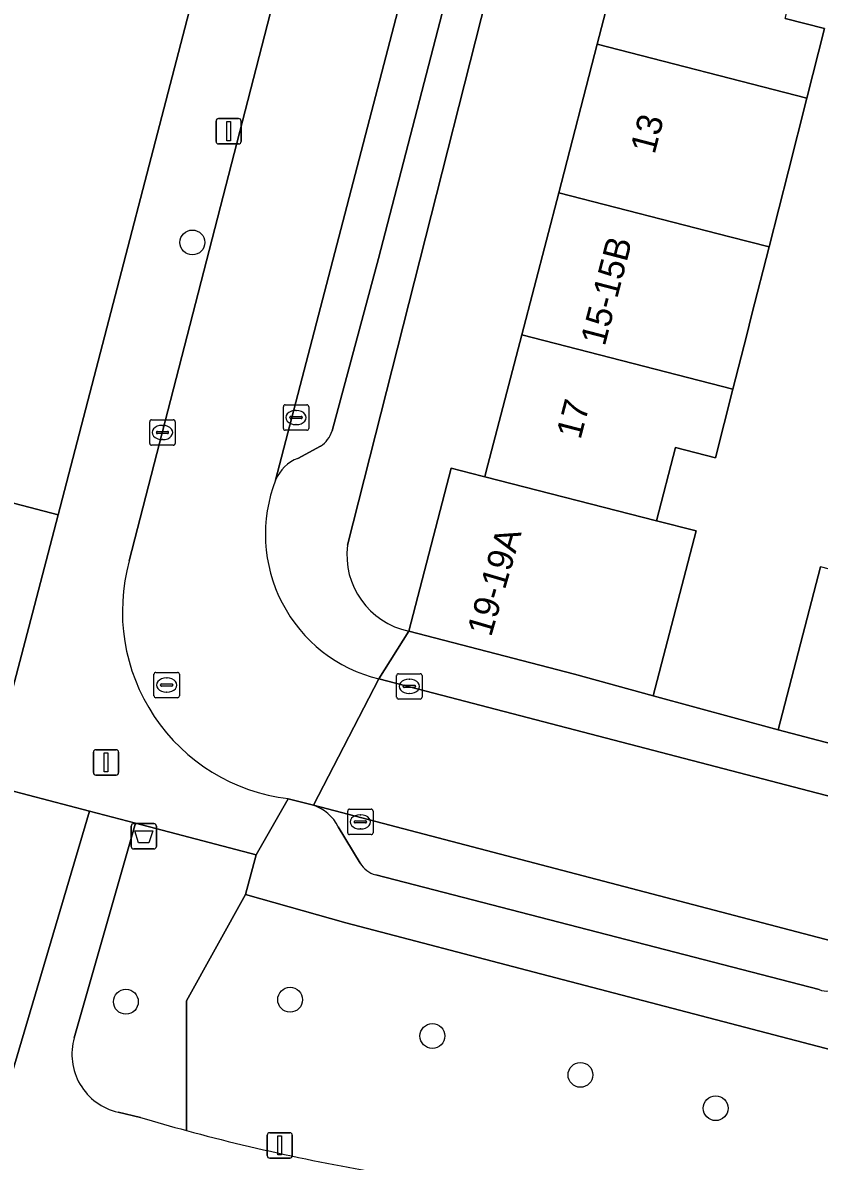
# Model space of a CAD drawing. Extents: x 163683 to 164494, y 382709 to 383872.
# Drawn here: x 164168.99 to 164200.33, y 383077.5 to 383122.29 of the extents above; entities that cross this region are included whole.
import ezdxf

# ---------------------------------------------------------------- set-up
doc = ezdxf.new("R2010")
doc.units = 0
for name, color, linetype in [('IMGEO_Afvalbak', 7, 'Continuous'), ('IMGEO_Boom', 7, 'Continuous'), ('IMGEO_Erf', 7, 'Continuous'), ('IMGEO_Groenvoorziening', 7, 'Continuous'), ('IMGEO_Kolk', 7, 'Continuous'), ('IMGEO_Lichtmast', 7, 'Continuous'), ('IMGEO_Muur', 7, 'Continuous'), ('IMGEO_Pand', 7, 'Continuous'), ('IMGEO_Pand_nummerreeks', 7, 'Continuous'), ('IMGEO_Parkeervlak_open', 7, 'Continuous'), ('IMGEO_Rijbaan_lokaal_open', 7, 'Continuous'), ('IMGEO_Rioolput', 7, 'Continuous'), ('IMGEO_Voetpad_halfverhard', 7, 'Continuous'), ('IMGEO_Voetpad_open', 7, 'Continuous')]:
    doc.layers.add(name, color=color, linetype=linetype)

msp = doc.modelspace()

# ---------------------------------------------------------------- linework, layer by layer
at = {"layer": 'IMGEO_Afvalbak'}
for p, q in [((164173.259, 383089.882), (164173.259, 383090.682)), ((164173.259, 383090.682), (164173.259, 383089.882)), ((164173.359, 383090.782), (164174.149, 383090.782)), ((164174.149, 383090.782), (164173.359, 383090.782)), ((164174.249, 383090.682), (164174.249, 383089.882)), ((164174.249, 383089.882), (164174.249, 383090.682)), ((164174.149, 383089.782), (164173.359, 383089.782)), ((164173.359, 383089.782), (164174.149, 383089.782))]:
    msp.add_line(p, q, dxfattribs=at)
msp.add_lwpolyline([(164173.402, 383090.496), (164174.106, 383090.496), (164173.957, 383090.026), (164173.551, 383090.026), (164173.402, 383090.496)], dxfattribs=at)
for centre, start, end in [((164173.359, 383090.682), 90, 180), ((164173.359, 383090.682), 90, 180), ((164174.149, 383090.682), 0, 90), ((164174.149, 383090.682), 360, 90), ((164173.359, 383089.882), 180, 270), ((164173.359, 383089.882), 180, 270), ((164174.149, 383089.882), 270, 0), ((164174.149, 383089.882), 270, 0)]:
    msp.add_arc(centre, 0.1, start, end, dxfattribs=at)
at = {"layer": 'IMGEO_Boom'}
for centre in [(164175.667, 383113.644), (164173.05, 383083.771), (164179.513, 383083.851), (164185.111, 383082.424), (164190.938, 383080.895), (164196.258, 383079.583)]:
    msp.add_circle(centre, 0.489, dxfattribs=at)
at = {"layer": 'IMGEO_Erf'}
for points in [[(164235.416, 383087.174), (164249.772, 383143.475), (164225.172, 383149.691), (164224.38, 383146.62), (164220.869, 383147.526), (164218.278, 383138.676), (164221.781, 383137.775), (164221.055, 383134.95), (164220.387, 383132.353), (164217.268, 383133.155), (164217.081, 383132.425), (164215.494, 383132.833), (164216.241, 383135.98), (164212.881, 383136.834), (164213.61, 383139.702), (164214.266, 383142.284), (164217.626, 383141.431), (164219.349, 383147.981), (164215.956, 383148.856), (164216.694, 383151.712), (164199.271, 383156.404), (164196.004, 383157.255), (164190.094, 383134.558), (164181.769, 383101.734)], [(164184.184, 383098.352), (164185.85, 383104.765), (164187.07, 383104.45), (164187.177, 383104.422), (164187.22, 383104.589), (164188.627, 383110.009), (164190.08, 383115.601), (164191.597, 383121.443), (164193.013, 383126.897)], [(164198.994, 383122.461), (164200.544, 383122.066), (164199.846, 383119.322), (164199.119, 383116.464), (164198.358, 383113.473), (164197.67, 383110.766), (164197.479, 383110.016), (164196.934, 383107.873), (164196.247, 383105.17), (164194.679, 383105.577), (164193.928, 383102.686), (164195.489, 383102.294), (164193.804, 383095.809), (164198.713, 383094.463), (164200.381, 383100.884)]]:
    msp.add_lwpolyline(points, dxfattribs=at)
msp.add_arc((164184.81, 383101.352), 3.065, 172.8489, 258.2105, dxfattribs=at)
at = {"layer": 'IMGEO_Groenvoorziening'}
for points in [[(164176.537, 383126.569), (164154.315, 383132.306), (164153.975, 383138.872), (164152.776, 383139.237), (164150.9, 383131.848), (164147.04, 383116.646), (164145.764, 383116.973), (164145.551, 383116.143), (164148.108, 383115.477), (164150.025, 383115.042), (164150.47, 383114.883), (164148.895, 383108.547), (164170.385, 383102.927)], [(164130.601, 383105.021), (164153.924, 383098.841), (164168.382, 383095.258), (164169.377, 383099.053), (164170.385, 383102.927), (164148.895, 383108.547), (164150.47, 383114.883), (164150.025, 383115.042), (164148.108, 383115.477), (164145.551, 383116.143), (164143.667, 383108.811), (164132.278, 383111.736)]]:
    msp.add_lwpolyline(points, close=True, dxfattribs=at)
for points in [[(164168.497, 383080.71), (164171.615, 383091.268), (164167.61, 383092.316), (164165.451, 383091.845)], [(164177.759, 383087.988), (164178.183, 383089.55), (164173.426, 383090.794), (164171.016, 383082.356)], [(164184.316, 383076.837), (164200.329, 383074.759), (164202.426, 383081.458), (164200.547, 383081.949), (164189.122, 383084.931), (164181.701, 383086.88), (164177.759, 383087.988), (164175.432, 383083.801), (164175.432, 383078.705)], [(164175.432, 383078.705), (164175.432, 383083.801), (164177.759, 383087.988)], [(164172.74, 383079.423), (164173.631, 383079.214)]]:
    msp.add_lwpolyline(points, dxfattribs=at)
for centre, radius, start, end in [((164173.276, 383081.711), 2.35, 164.0721, 256.8215), ((164195.419, 383152.866), 76.807, 253.52053, 254.91668), ((164196.337, 383156.069), 80.139, 254.87862, 261.37267)]:
    msp.add_arc(centre, radius, start, end, dxfattribs=at)
at = {"layer": 'IMGEO_Kolk'}
for p, q in [((164179.246, 383106.331), (164179.246, 383107.183)), ((164179.321, 383107.257), (164180.173, 383107.257)), ((164180.247, 383107.183), (164180.247, 383106.331)), ((164174.064, 383106.667), (164174.916, 383106.667)), ((164179.505, 383106.751), (164179.505, 383106.763)), ((164179.943, 383106.714), (164179.545, 383106.714)), ((164179.548, 383106.8), (164179.946, 383106.8)), ((164179.734, 383107.037), (164179.759, 383107.037)), ((164179.989, 383106.763), (164179.989, 383106.751)), ((164173.989, 383105.741), (164173.989, 383106.593)), ((164174.291, 383106.21), (164174.689, 383106.21)), ((164174.477, 383106.447), (164174.502, 383106.447)), ((164174.99, 383106.593), (164174.99, 383105.741)), ((164180.173, 383106.257), (164179.321, 383106.257)), ((164179.757, 383106.477), (164179.732, 383106.477)), ((164174.248, 383106.161), (164174.248, 383106.173)), ((164174.686, 383106.124), (164174.288, 383106.124)), ((164174.5, 383105.887), (164174.475, 383105.887)), ((164174.732, 383106.173), (164174.732, 383106.161)), ((164174.916, 383105.667), (164174.064, 383105.667)), ((164183.705, 383095.752), (164183.705, 383096.604)), ((164183.78, 383096.678), (164184.632, 383096.678)), ((164184.193, 383096.458), (164184.218, 383096.458)), ((164184.706, 383096.604), (164184.706, 383095.752)), ((164183.964, 383096.172), (164183.964, 383096.184)), ((164184.402, 383096.135), (164184.004, 383096.135)), ((164184.007, 383096.221), (164184.405, 383096.221)), ((164184.216, 383095.898), (164184.191, 383095.898)), ((164184.448, 383096.184), (164184.448, 383096.172)), ((164184.632, 383095.678), (164183.78, 383095.678)), ((164181.778, 383090.422), (164181.778, 383091.274)), ((164181.853, 383091.348), (164182.705, 383091.348)), ((164182.266, 383091.128), (164182.291, 383091.128)), ((164182.779, 383091.274), (164182.779, 383090.422)), ((164182.037, 383090.842), (164182.037, 383090.854)), ((164182.475, 383090.805), (164182.077, 383090.805)), ((164182.08, 383090.891), (164182.478, 383090.891)), ((164182.289, 383090.568), (164182.264, 383090.568)), ((164182.521, 383090.854), (164182.521, 383090.842)), ((164182.705, 383090.348), (164181.853, 383090.348))]:
    msp.add_line(p, q, dxfattribs=at)
for points in [[(164179.246, 383106.331), (164179.246, 383107.183)], [(164179.321, 383107.257), (164180.173, 383107.257)], [(164180.247, 383107.183), (164180.247, 383106.331)], [(164174.064, 383106.667), (164174.916, 383106.667)], [(164173.989, 383105.741), (164173.989, 383106.593)], [(164174.99, 383106.593), (164174.99, 383105.741)], [(164180.173, 383106.257), (164179.321, 383106.257)], [(164174.916, 383105.667), (164174.064, 383105.667)], [(164183.705, 383095.752), (164183.705, 383096.604)], [(164183.78, 383096.678), (164184.632, 383096.678)], [(164184.706, 383096.604), (164184.706, 383095.752)], [(164184.632, 383095.678), (164183.78, 383095.678)], [(164181.778, 383090.422), (164181.778, 383091.274)], [(164181.853, 383091.348), (164182.705, 383091.348)], [(164182.779, 383091.274), (164182.779, 383090.422)], [(164182.705, 383090.348), (164181.853, 383090.348)]]:
    msp.add_lwpolyline(points, dxfattribs=at)
for centre, radius, start, end in [((164179.323, 383107.181), 0.0765, 91.552, 178.448), ((164179.323, 383107.181), 0.0765, 91.552, 178.448), ((164180.171, 383107.181), 0.0765, 1.552, 88.448), ((164180.171, 383107.181), 0.0765, 1.552, 88.448), ((164174.066, 383106.591), 0.0765, 91.552, 178.448), ((164174.066, 383106.591), 0.0765, 91.552, 178.448), ((164174.914, 383106.591), 0.0765, 1.552, 88.448), ((164174.914, 383106.591), 0.0765, 1.552, 88.448), ((164179.545, 383106.76), 0.0403, 85.8775, 175.7526), ((164179.542, 383106.75), 0.0366, 178.938, 274.7102), ((164179.946, 383106.757), 0.043, 264.8664, 352.4533), ((164179.95, 383106.762), 0.0386, 1.7309, 96.639), ((164174.288, 383106.17), 0.0403, 85.8775, 175.7526), ((164174.693, 383106.172), 0.0386, 1.7309, 96.639), ((164179.323, 383106.333), 0.0765, 181.552, 268.448), ((164179.323, 383106.333), 0.0765, 181.552, 268.448), ((164180.171, 383106.333), 0.0765, 271.552, 358.448), ((164180.171, 383106.333), 0.0765, 271.552, 358.448), ((164174.066, 383105.743), 0.0765, 181.552, 268.448), ((164174.066, 383105.743), 0.0765, 181.552, 268.448), ((164174.285, 383106.16), 0.0366, 178.938, 274.7102), ((164174.689, 383106.167), 0.043, 264.8664, 352.4533), ((164174.914, 383105.743), 0.0765, 271.552, 358.448), ((164174.914, 383105.743), 0.0765, 271.552, 358.448), ((164183.782, 383096.602), 0.0765, 91.552, 178.448), ((164183.782, 383096.602), 0.0765, 91.552, 178.448), ((164184.63, 383096.602), 0.0765, 1.552, 88.448), ((164184.63, 383096.602), 0.0765, 1.552, 88.448), ((164184.004, 383096.181), 0.0403, 85.8775, 175.7526), ((164184.001, 383096.171), 0.0366, 178.938, 274.7102), ((164184.405, 383096.178), 0.043, 264.8664, 352.4533), ((164184.409, 383096.183), 0.0386, 1.7309, 96.639), ((164183.782, 383095.754), 0.0765, 181.552, 268.448), ((164183.782, 383095.754), 0.0765, 181.552, 268.448), ((164184.63, 383095.754), 0.0765, 271.552, 358.448), ((164184.63, 383095.754), 0.0765, 271.552, 358.448), ((164181.855, 383091.272), 0.0765, 91.552, 178.448), ((164181.855, 383091.272), 0.0765, 91.552, 178.448), ((164182.703, 383091.272), 0.0765, 1.552, 88.448), ((164182.703, 383091.272), 0.0765, 1.552, 88.448), ((164182.077, 383090.851), 0.0403, 85.8775, 175.7526), ((164182.074, 383090.841), 0.0366, 178.938, 274.7102), ((164182.478, 383090.848), 0.043, 264.8664, 352.4533), ((164182.482, 383090.853), 0.0386, 1.7309, 96.639), ((164181.855, 383090.424), 0.0765, 181.552, 268.448), ((164181.855, 383090.424), 0.0765, 181.552, 268.448), ((164182.703, 383090.424), 0.0765, 271.552, 358.448), ((164182.703, 383090.424), 0.0765, 271.552, 358.448)]:
    msp.add_arc(centre, radius, start, end, dxfattribs=at)
for centre, major_axis, ratio, start_param, end_param in [((164179.733, 383106.757), (-0.387, 0.002), 0.722429, 4.712389, 7.853982), ((164179.758, 383106.757), (-0.39, 0.002), 0.717154, 1.570796, 4.712389), ((164174.476, 383106.167), (-0.387, 0.002), 0.722429, 4.712389, 7.853982), ((164174.501, 383106.167), (-0.39, 0.002), 0.717154, 1.570796, 4.712389), ((164184.192, 383096.178), (-0.387, 0.002), 0.722429, 4.712389, 7.853982), ((164184.217, 383096.178), (-0.39, 0.002), 0.717154, 1.570796, 4.712389), ((164182.265, 383090.848), (-0.387, 0.002), 0.722429, 4.712389, 7.853982), ((164182.29, 383090.848), (-0.39, 0.002), 0.717154, 1.570796, 4.712389)]:
    msp.add_ellipse(centre, major_axis=major_axis, ratio=ratio, start_param=start_param, end_param=end_param, dxfattribs=at)
at = {"layer": 'IMGEO_Lichtmast'}
for p, q in [((164176.597, 383117.622), (164176.597, 383118.422)), ((164176.597, 383118.422), (164176.597, 383117.622)), ((164176.697, 383118.522), (164177.487, 383118.522)), ((164177.487, 383118.522), (164176.697, 383118.522)), ((164177.587, 383118.422), (164177.587, 383117.622)), ((164177.587, 383117.622), (164177.587, 383118.422)), ((164177.487, 383117.522), (164176.697, 383117.522)), ((164176.697, 383117.522), (164177.487, 383117.522)), ((164171.873, 383093.687), (164172.663, 383093.687)), ((164172.663, 383093.687), (164171.873, 383093.687)), ((164171.773, 383092.787), (164171.773, 383093.587)), ((164171.773, 383093.587), (164171.773, 383092.787)), ((164172.763, 383093.587), (164172.763, 383092.787)), ((164172.763, 383092.787), (164172.763, 383093.587)), ((164172.663, 383092.687), (164171.873, 383092.687)), ((164171.873, 383092.687), (164172.663, 383092.687)), ((164178.609, 383077.717), (164178.609, 383078.517)), ((164178.609, 383078.517), (164178.609, 383077.717)), ((164178.709, 383078.617), (164179.499, 383078.617)), ((164179.499, 383078.617), (164178.709, 383078.617)), ((164179.599, 383078.517), (164179.599, 383077.717)), ((164179.599, 383077.717), (164179.599, 383078.517)), ((164179.499, 383077.617), (164178.709, 383077.617)), ((164178.709, 383077.617), (164179.499, 383077.617))]:
    msp.add_line(p, q, dxfattribs=at)
for points in [[(164177.017, 383118.397), (164177.167, 383118.397), (164177.167, 383117.647), (164177.017, 383117.647), (164177.017, 383118.397)], [(164172.193, 383093.562), (164172.343, 383093.562), (164172.343, 383092.812), (164172.193, 383092.812), (164172.193, 383093.562)], [(164179.029, 383078.492), (164179.179, 383078.492), (164179.179, 383077.742), (164179.029, 383077.742), (164179.029, 383078.492)]]:
    msp.add_lwpolyline(points, dxfattribs=at)
for centre, start, end in [((164176.697, 383118.422), 90, 180), ((164176.697, 383118.422), 90, 180), ((164177.487, 383118.422), 0, 90), ((164177.487, 383118.422), 360, 90), ((164176.697, 383117.622), 180, 270), ((164176.697, 383117.622), 180, 270), ((164177.487, 383117.622), 270, 0), ((164177.487, 383117.622), 270, 0), ((164171.873, 383093.587), 90, 180), ((164171.873, 383093.587), 90, 180), ((164172.663, 383093.587), 0, 90), ((164172.663, 383093.587), 360, 90), ((164171.873, 383092.787), 180, 270), ((164171.873, 383092.787), 180, 270), ((164172.663, 383092.787), 270, 0), ((164172.663, 383092.787), 270, 0), ((164178.709, 383078.517), 90, 180), ((164178.709, 383078.517), 90, 180), ((164179.499, 383078.517), 0, 90), ((164179.499, 383078.517), 360, 90), ((164178.709, 383077.717), 180, 270), ((164178.709, 383077.717), 180, 270), ((164179.499, 383077.717), 270, 0), ((164179.499, 383077.717), 270, 0)]:
    msp.add_arc(centre, 0.1, start, end, dxfattribs=at)
at = {"layer": 'IMGEO_Muur'}
msp.add_lwpolyline([(164193.804, 383095.809), (164198.713, 383094.463)], dxfattribs=at)
at = {"layer": 'IMGEO_Pand'}
for points in [[(164199.846, 383119.322), (164200.544, 383122.066), (164198.994, 383122.461), (164199.676, 383125.184), (164193.013, 383126.897), (164191.597, 383121.443)], [(164199.846, 383119.322), (164191.597, 383121.443), (164190.08, 383115.601), (164196.809, 383113.871), (164198.358, 383113.473), (164199.119, 383116.464)], [(164198.358, 383113.473), (164196.809, 383113.871), (164190.08, 383115.601), (164188.627, 383110.009), (164196.934, 383107.873), (164197.479, 383110.016), (164197.67, 383110.766)], [(164194.679, 383105.577), (164196.247, 383105.17), (164196.934, 383107.873), (164188.627, 383110.009), (164187.22, 383104.589), (164187.177, 383104.422), (164193.928, 383102.686)], [(164195.489, 383102.294), (164193.928, 383102.686), (164187.177, 383104.422), (164187.07, 383104.45), (164185.85, 383104.765), (164184.184, 383098.352), (164190.698, 383096.66), (164193.804, 383095.809)], [(164201.862, 383093.645), (164203.53, 383100.066), (164200.381, 383100.884), (164198.713, 383094.463)]]:
    msp.add_lwpolyline(points, close=True, dxfattribs=at)
at = {"layer": 'IMGEO_Parkeervlak_open'}
for points in [[(164181.165, 383106.231), (164182.993, 383113.017), (164188.276, 383133.387), (164186.93, 383133.713), (164187.272, 383134.967), (164188.588, 383134.63), (164190.203, 383140.877), (164188.616, 383141.38), (164184.638, 383126.187), (164178.941, 383104.293)], [(164179.817, 383105.151), (164180.712, 383105.627)], [(164227.179, 383079.262), (164180.429, 383091.502)], [(164181.407, 383090.659), (164182.27, 383089.23)], [(164182.88, 383088.767), (164200.333, 383084.249)]]:
    msp.add_lwpolyline(points, dxfattribs=at)
for centre, radius, start, end in [((164180.073, 383106.578), 1.145, 303.8856, 342.3746), ((164180.38, 383103.7), 1.556, 111.2012, 157.6093), ((164179.865, 383089.859), 1.737, 27.4154, 71.0643), ((164183.088, 383089.674), 0.931, 208.5109, 257.0909), ((164200.618, 383084.951), 0.758, 247.9282, 307.1195)]:
    msp.add_arc(centre, radius, start, end, dxfattribs=at)
at = {"layer": 'IMGEO_Rijbaan_lokaal_open'}
for points in [[(164184.638, 383126.187), (164179.925, 383127.281), (164173.185, 383101.113)], [(164178.941, 383104.293), (164184.638, 383126.187)], [(164179.441, 383091.761), (164180.429, 383091.502), (164183.001, 383096.472)], [(164232.76, 383083.491), (164210.131, 383089.408), (164205.194, 383090.692), (164183.001, 383096.472), (164180.429, 383091.502), (164227.179, 383079.262), (164228.673, 383078.974), (164230.667, 383078.411), (164236.737, 383076.868)]]:
    msp.add_lwpolyline(points, dxfattribs=at)
for centre, radius, start, end in [((164184.397, 383102.161), 5.858, 158.6549, 256.2142), ((164180.328, 383099.123), 7.415, 164.4345, 263.1264)]:
    msp.add_arc(centre, radius, start, end, dxfattribs=at)
at = {"layer": 'IMGEO_Rioolput'}
for p, q in [((164174.156, 383095.804), (164174.156, 383096.656)), ((164174.231, 383096.73), (164175.083, 383096.73)), ((164174.644, 383096.51), (164174.669, 383096.51)), ((164175.157, 383096.656), (164175.157, 383095.804)), ((164174.415, 383096.224), (164174.415, 383096.236)), ((164174.853, 383096.187), (164174.455, 383096.187)), ((164174.458, 383096.273), (164174.856, 383096.273)), ((164174.667, 383095.95), (164174.642, 383095.95)), ((164174.899, 383096.236), (164174.899, 383096.224)), ((164175.083, 383095.73), (164174.231, 383095.73))]:
    msp.add_line(p, q, dxfattribs=at)
for points in [[(164174.156, 383095.804), (164174.156, 383096.656)], [(164174.231, 383096.73), (164175.083, 383096.73)], [(164175.157, 383096.656), (164175.157, 383095.804)], [(164175.083, 383095.73), (164174.231, 383095.73)]]:
    msp.add_lwpolyline(points, dxfattribs=at)
for centre, radius, start, end in [((164174.233, 383096.654), 0.0765, 91.552, 178.448), ((164174.233, 383096.654), 0.0765, 91.552, 178.448), ((164175.081, 383096.654), 0.0765, 1.552, 88.448), ((164175.081, 383096.654), 0.0765, 1.552, 88.448), ((164174.455, 383096.233), 0.0403, 85.8775, 175.7526), ((164174.452, 383096.223), 0.0366, 178.938, 274.7102), ((164174.856, 383096.23), 0.043, 264.8664, 352.4533), ((164174.86, 383096.235), 0.0386, 1.7309, 96.639), ((164174.233, 383095.806), 0.0765, 181.552, 268.448), ((164174.233, 383095.806), 0.0765, 181.552, 268.448), ((164175.081, 383095.806), 0.0765, 271.552, 358.448), ((164175.081, 383095.806), 0.0765, 271.552, 358.448)]:
    msp.add_arc(centre, radius, start, end, dxfattribs=at)
for centre, major_axis, ratio, start_param, end_param in [((164174.643, 383096.23), (-0.387, 0.002), 0.722429, 4.712389, 7.853982), ((164174.668, 383096.23), (-0.39, 0.002), 0.717154, 1.570796, 4.712389)]:
    msp.add_ellipse(centre, major_axis=major_axis, ratio=ratio, start_param=start_param, end_param=end_param, dxfattribs=at)
at = {"layer": 'IMGEO_Voetpad_halfverhard'}
for points in [[(164171.016, 383082.356), (164173.426, 383090.794), (164171.615, 383091.268), (164168.497, 383080.71)], [(164173.631, 383079.214), (164172.74, 383079.423)]]:
    msp.add_lwpolyline(points, dxfattribs=at)
for centre, radius, start, end in [((164173.276, 383081.711), 2.35, 164.0721, 256.8215), ((164195.419, 383152.866), 76.807, 253.52053, 254.91668), ((164196.337, 383156.069), 80.139, 254.87862, 261.37267)]:
    msp.add_arc(centre, radius, start, end, dxfattribs=at)
at = {"layer": 'IMGEO_Voetpad_open'}
for points in [[(164194.463, 383158.425), (164194.849, 383158.324), (164191.595, 383146.154), (164190.534, 383142.159), (164190.203, 383140.877), (164188.588, 383134.63), (164187.272, 383134.967), (164186.93, 383133.713), (164188.276, 383133.387), (164182.993, 383113.017), (164181.165, 383106.231)], [(164181.769, 383101.734), (164190.094, 383134.558)], [(164179.925, 383127.281), (164176.537, 383126.569), (164170.385, 383102.927), (164169.377, 383099.053), (164168.382, 383095.258), (164167.61, 383092.316), (164171.615, 383091.268), (164173.426, 383090.794), (164178.183, 383089.55), (164179.441, 383091.761)], [(164173.185, 383101.113), (164179.925, 383127.281)], [(164180.712, 383105.627), (164179.817, 383105.151)], [(164210.386, 383091.398), (164206.877, 383092.321), (164206.567, 383092.405), (164205.01, 383092.827), (164201.862, 383093.645), (164198.713, 383094.463), (164193.804, 383095.809), (164190.698, 383096.66), (164184.184, 383098.352), (164183.001, 383096.472), (164205.194, 383090.692), (164205.469, 383091.739), (164210.413, 383090.446), (164210.131, 383089.408), (164232.76, 383083.491)], [(164183.001, 383096.472), (164184.184, 383098.352)], [(164180.429, 383091.502), (164179.441, 383091.761), (164178.183, 383089.55), (164177.759, 383087.988), (164181.701, 383086.88), (164189.122, 383084.931), (164200.547, 383081.949), (164202.426, 383081.458), (164212.022, 383078.953), (164227.823, 383074.828), (164229.967, 383074.268), (164232.957, 383073.94)], [(164182.27, 383089.23), (164181.407, 383090.659)], [(164200.333, 383084.249), (164182.88, 383088.767)]]:
    msp.add_lwpolyline(points, dxfattribs=at)
for centre, radius, start, end in [((164180.073, 383106.578), 1.145, 303.8856, 342.3746), ((164180.38, 383103.7), 1.556, 111.2012, 157.6093), ((164184.397, 383102.161), 5.858, 158.6549, 256.2142), ((164184.81, 383101.352), 3.065, 172.8489, 258.2105), ((164180.328, 383099.123), 7.415, 164.4345, 263.1264), ((164179.865, 383089.859), 1.737, 27.4154, 71.0643), ((164183.088, 383089.674), 0.931, 208.5109, 257.0909), ((164200.618, 383084.951), 0.758, 247.9282, 307.1195)]:
    msp.add_arc(centre, radius, start, end, dxfattribs=at)

# ---------------------------------------------------------------- texts
at = {"layer": 'IMGEO_Pand_nummerreeks'}
for s, rotation, p in [('13', 75.4414, (164193.852, 383117.082)), ('15-15B', 75.4414, (164191.893, 383109.534)), ('17', 75.4414, (164190.938, 383105.859)), ('19-19A', 73.7053, (164187.418, 383098.094))]:
    msp.add_text(s, height=1, rotation=rotation, dxfattribs=at).set_placement(p)

doc.saveas('drawing.dxf')
